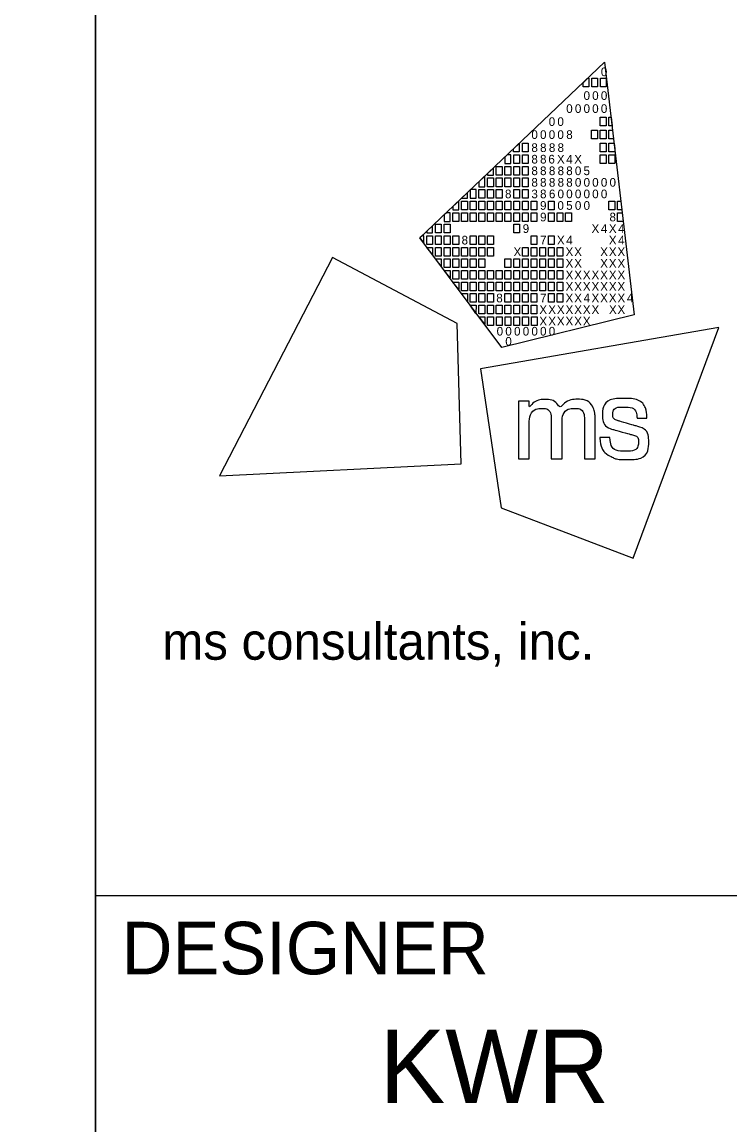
# Model space of a CAD drawing. Extents: x -0.2 to 34, y 6.6 to 28.6.
# Drawn here: x 31.86 to 33.207, y 8.674 to 10.773 of the extents above; entities that cross this region are included whole.
import ezdxf

# ---------------------------------------------------------------- set-up
doc = ezdxf.new("R2010")
doc.units = 0
for name, color, linetype in [('GE_X_Alignment', 7, 'Continuous'), ('SH_Border', 7, 'Continuous'), ('SH_Data', 7, 'Continuous')]:
    doc.layers.add(name, color=color, linetype=linetype)

msp = doc.modelspace()

# ---------------------------------------------------------------- linework, layer by layer
at = {"layer": 'GE_X_Alignment'}
msp.add_lwpolyline([(1.5, 28.1108), (32, 28.1108), (32, 7.1108), (1.5, 7.1108)], close=True, dxfattribs=at)
at = {"layer": 'SH_Border'}
for p, q in [((32, 7.1108), (32, 28.1108)), ((32, 9.1108), (33.5, 9.1108))]:
    msp.add_line(p, q, dxfattribs=at)
at = {"layer": 'SH_Data'}
for p, q in [((32.6175, 10.3627), (32.9688, 10.6969)), ((32.9688, 10.6969), (32.9688, 10.6969)), ((32.9688, 10.6969), (33.0253, 10.2159)), ((32.773, 10.1538), (32.6175, 10.3627)), ((33.0253, 10.2159), (32.773, 10.1538)), ((32.75, 10.1108), (32.75, 10.1108))]:
    msp.add_line(p, q, dxfattribs=at)
for points in [[(32.9279, 10.658), (32.9369, 10.6666), (32.9389, 10.6666), (32.9389, 10.6501), (32.9279, 10.6501)], [(32.9444, 10.6666), (32.9554, 10.6666), (32.9554, 10.6501), (32.9444, 10.6501)], [(32.9609, 10.6666), (32.9719, 10.6666), (32.9719, 10.6501), (32.9609, 10.6501)], [(32.9606, 10.5923), (32.9716, 10.5923), (32.9716, 10.5757), (32.9606, 10.5757)], [(32.9771, 10.5923), (32.9811, 10.5923), (32.983, 10.5757), (32.9771, 10.5757)], [(32.9441, 10.5675), (32.9551, 10.5675), (32.9551, 10.551), (32.9441, 10.551)], [(32.9606, 10.5675), (32.9716, 10.5675), (32.9716, 10.551), (32.9606, 10.551)], [(32.9771, 10.5675), (32.984, 10.5675), (32.9859, 10.551), (32.9771, 10.551)], [(32.7953, 10.5319), (32.8064, 10.5424), (32.8064, 10.5262), (32.7953, 10.5262)], [(32.8123, 10.5427), (32.8233, 10.5427), (32.8233, 10.5262), (32.8123, 10.5262)], [(32.9606, 10.5427), (32.9716, 10.5427), (32.9716, 10.5262), (32.9606, 10.5262)], [(32.9771, 10.5427), (32.9869, 10.5427), (32.9881, 10.5326), (32.9881, 10.5262), (32.9771, 10.5262)], [(32.7958, 10.5207), (32.8068, 10.5207), (32.8068, 10.5042), (32.7958, 10.5042)], [(32.8123, 10.5207), (32.8233, 10.5207), (32.8233, 10.5042), (32.8123, 10.5042)], [(32.9606, 10.5207), (32.9716, 10.5207), (32.9716, 10.5042), (32.9606, 10.5042)], [(32.9771, 10.5207), (32.9881, 10.5207), (32.9881, 10.5042), (32.9771, 10.5042)], [(32.7627, 10.4987), (32.7737, 10.4987), (32.7737, 10.4822), (32.7627, 10.4822)], [(32.7793, 10.4987), (32.7903, 10.4987), (32.7903, 10.4822), (32.7793, 10.4822)], [(32.7958, 10.4987), (32.8068, 10.4987), (32.8068, 10.4822), (32.7958, 10.4822)], [(32.8123, 10.4987), (32.8233, 10.4987), (32.8233, 10.4822), (32.8123, 10.4822)], [(32.7462, 10.4767), (32.7572, 10.4767), (32.7572, 10.4601), (32.7462, 10.4601)], [(32.7627, 10.4767), (32.7737, 10.4767), (32.7737, 10.4601), (32.7627, 10.4601)], [(32.7793, 10.4767), (32.7903, 10.4767), (32.7903, 10.4601), (32.7793, 10.4601)], [(32.7958, 10.4767), (32.8068, 10.4767), (32.8068, 10.4601), (32.7958, 10.4601)], [(32.8123, 10.4767), (32.8233, 10.4767), (32.8233, 10.4601), (32.8123, 10.4601)], [(32.7297, 10.4546), (32.7407, 10.4546), (32.7407, 10.4381), (32.7297, 10.4381)], [(32.7462, 10.4546), (32.7572, 10.4546), (32.7572, 10.4381), (32.7462, 10.4381)], [(32.7627, 10.4546), (32.7737, 10.4546), (32.7737, 10.4381), (32.7627, 10.4381)], [(32.7958, 10.4546), (32.8068, 10.4546), (32.8068, 10.4381), (32.7958, 10.4381)], [(32.8123, 10.4546), (32.8233, 10.4546), (32.8233, 10.4381), (32.8123, 10.4381)], [(32.6967, 10.4326), (32.7077, 10.4326), (32.7077, 10.4161), (32.6967, 10.4161)], [(32.7132, 10.4326), (32.7242, 10.4326), (32.7242, 10.4161), (32.7132, 10.4161)], [(32.7297, 10.4326), (32.7407, 10.4326), (32.7407, 10.4161), (32.7297, 10.4161)], [(32.7462, 10.4326), (32.7572, 10.4326), (32.7572, 10.4161), (32.7462, 10.4161)], [(32.7627, 10.4326), (32.7737, 10.4326), (32.7737, 10.4161), (32.7627, 10.4161)], [(32.7793, 10.4326), (32.7903, 10.4326), (32.7903, 10.4161), (32.7793, 10.4161)], [(32.7958, 10.4326), (32.8068, 10.4326), (32.8068, 10.4161), (32.7958, 10.4161)], [(32.8123, 10.4326), (32.8233, 10.4326), (32.8233, 10.4161), (32.8123, 10.4161)], [(32.8288, 10.4326), (32.8398, 10.4326), (32.8398, 10.4161), (32.8288, 10.4161)], [(32.8618, 10.4326), (32.8728, 10.4326), (32.8728, 10.4161), (32.8618, 10.4161)], [(32.9771, 10.4326), (32.9881, 10.4326), (32.9881, 10.4161), (32.9771, 10.4161)], [(32.9935, 10.4326), (32.9998, 10.4326), (33.0018, 10.4161), (32.9935, 10.4161)], [(32.6802, 10.4106), (32.6912, 10.4106), (32.6912, 10.3941), (32.6802, 10.3941)], [(32.6967, 10.4106), (32.7077, 10.4106), (32.7077, 10.3941), (32.6967, 10.3941)], [(32.7132, 10.4106), (32.7242, 10.4106), (32.7242, 10.3941), (32.7132, 10.3941)], [(32.7297, 10.4106), (32.7407, 10.4106), (32.7407, 10.3941), (32.7297, 10.3941)], [(32.7462, 10.4106), (32.7572, 10.4106), (32.7572, 10.3941), (32.7462, 10.3941)], [(32.7627, 10.4106), (32.7737, 10.4106), (32.7737, 10.3941), (32.7627, 10.3941)], [(32.7793, 10.4106), (32.7903, 10.4106), (32.7903, 10.3941), (32.7793, 10.3941)], [(32.7958, 10.4106), (32.8068, 10.4106), (32.8068, 10.3941), (32.7958, 10.3941)], [(32.8123, 10.4106), (32.8233, 10.4106), (32.8233, 10.3941), (32.8123, 10.3941)], [(32.8288, 10.4106), (32.8398, 10.4106), (32.8398, 10.3941), (32.8288, 10.3941)], [(32.8618, 10.4106), (32.8728, 10.4106), (32.8728, 10.3941), (32.8618, 10.3941)], [(32.8783, 10.4106), (32.8893, 10.4106), (32.8893, 10.3941), (32.8783, 10.3941)], [(32.8947, 10.4106), (32.9057, 10.4106), (32.9057, 10.3941), (32.8947, 10.3941)], [(32.9935, 10.4106), (33.0024, 10.4106), (33.0044, 10.3941), (32.9935, 10.3941)], [(32.6471, 10.3886), (32.6581, 10.3886), (32.6581, 10.3721), (32.6471, 10.3721)], [(32.6637, 10.3886), (32.6747, 10.3886), (32.6747, 10.3721), (32.6637, 10.3721)], [(32.7958, 10.3886), (32.8068, 10.3886), (32.8068, 10.3721), (32.7958, 10.3721)], [(32.6306, 10.3666), (32.6416, 10.3666), (32.6416, 10.3501), (32.6306, 10.3501)], [(32.6471, 10.3666), (32.6581, 10.3666), (32.6581, 10.3501), (32.6471, 10.3501)], [(32.6637, 10.3666), (32.6747, 10.3666), (32.6747, 10.3501), (32.6637, 10.3501)], [(32.6802, 10.3666), (32.6912, 10.3666), (32.6912, 10.3501), (32.6802, 10.3501)], [(32.7132, 10.3666), (32.7242, 10.3666), (32.7242, 10.3501), (32.7132, 10.3501)], [(32.7297, 10.3666), (32.7407, 10.3666), (32.7407, 10.3501), (32.7297, 10.3501)], [(32.7462, 10.3666), (32.7572, 10.3666), (32.7572, 10.3501), (32.7462, 10.3501)], [(32.8288, 10.3666), (32.8398, 10.3666), (32.8398, 10.3501), (32.8288, 10.3501)], [(32.8618, 10.3666), (32.8728, 10.3666), (32.8728, 10.3501), (32.8618, 10.3501)], [(32.6306, 10.3445), (32.6416, 10.3445), (32.6416, 10.3308)], [(32.6471, 10.3445), (32.6581, 10.3445), (32.6581, 10.328), (32.6471, 10.328)], [(32.6637, 10.3445), (32.6747, 10.3445), (32.6747, 10.328), (32.6637, 10.328)], [(32.6802, 10.3445), (32.6912, 10.3445), (32.6912, 10.328), (32.6802, 10.328)], [(32.6967, 10.3445), (32.7077, 10.3445), (32.7077, 10.328), (32.6967, 10.328)], [(32.7132, 10.3445), (32.7242, 10.3445), (32.7242, 10.328), (32.7132, 10.328)], [(32.7297, 10.3445), (32.7407, 10.3445), (32.7407, 10.328), (32.7297, 10.328)], [(32.7462, 10.3445), (32.7572, 10.3445), (32.7572, 10.328), (32.7462, 10.328)], [(32.8123, 10.3445), (32.8233, 10.3445), (32.8233, 10.328), (32.8123, 10.328)], [(32.8288, 10.3445), (32.8398, 10.3445), (32.8398, 10.328), (32.8288, 10.328)], [(32.8453, 10.3445), (32.8563, 10.3445), (32.8563, 10.328), (32.8453, 10.328)], [(32.8618, 10.3445), (32.8728, 10.3445), (32.8728, 10.328), (32.8618, 10.328)], [(32.8783, 10.3445), (32.8893, 10.3445), (32.8893, 10.328), (32.8783, 10.328)], [(32.6471, 10.3225), (32.6581, 10.3225), (32.6581, 10.3088)], [(32.6637, 10.3225), (32.6747, 10.3225), (32.6747, 10.306), (32.6637, 10.306)], [(32.6802, 10.3225), (32.6912, 10.3225), (32.6912, 10.306), (32.6802, 10.306)], [(32.6967, 10.3225), (32.7077, 10.3225), (32.7077, 10.306), (32.6967, 10.306)], [(32.7132, 10.3225), (32.7242, 10.3225), (32.7242, 10.306), (32.7132, 10.306)], [(32.7297, 10.3225), (32.7407, 10.3225), (32.7407, 10.306), (32.7297, 10.306)], [(32.7793, 10.3225), (32.7903, 10.3225), (32.7903, 10.306), (32.7793, 10.306)], [(32.7958, 10.3225), (32.8068, 10.3225), (32.8068, 10.306), (32.7958, 10.306)], [(32.8123, 10.3225), (32.8233, 10.3225), (32.8233, 10.306), (32.8123, 10.306)], [(32.8288, 10.3225), (32.8398, 10.3225), (32.8398, 10.306), (32.8288, 10.306)], [(32.8453, 10.3225), (32.8563, 10.3225), (32.8563, 10.306), (32.8453, 10.306)], [(32.8618, 10.3225), (32.8728, 10.3225), (32.8728, 10.306), (32.8618, 10.306)], [(32.8783, 10.3225), (32.8893, 10.3225), (32.8893, 10.306), (32.8783, 10.306)], [(32.6637, 10.3005), (32.6747, 10.3005), (32.6747, 10.2868)], [(32.6747, 10.3005), (32.6747, 10.3005), (32.6747, 10.3005)], [(32.6802, 10.3005), (32.6912, 10.3005), (32.6912, 10.284), (32.6802, 10.284)], [(32.6967, 10.3005), (32.7077, 10.3005), (32.7077, 10.284), (32.6967, 10.284)], [(32.7132, 10.3005), (32.7242, 10.3005), (32.7242, 10.284), (32.7132, 10.284)], [(32.7297, 10.3005), (32.7407, 10.3005), (32.7407, 10.284), (32.7297, 10.284)], [(32.7462, 10.3005), (32.7572, 10.3005), (32.7572, 10.284), (32.7462, 10.284)], [(32.7627, 10.3005), (32.7737, 10.3005), (32.7737, 10.284), (32.7627, 10.284)], [(32.7793, 10.3005), (32.7903, 10.3005), (32.7903, 10.284), (32.7793, 10.284)], [(32.7958, 10.3005), (32.8068, 10.3005), (32.8068, 10.284), (32.7958, 10.284)], [(32.8123, 10.3005), (32.8233, 10.3005), (32.8233, 10.284), (32.8123, 10.284)], [(32.8288, 10.3005), (32.8398, 10.3005), (32.8398, 10.284), (32.8288, 10.284)], [(32.8453, 10.3005), (32.8563, 10.3005), (32.8563, 10.284), (32.8453, 10.284)], [(32.8618, 10.3005), (32.8728, 10.3005), (32.8728, 10.284), (32.8618, 10.284)], [(32.8783, 10.3005), (32.8893, 10.3005), (32.8893, 10.284), (32.8783, 10.284)], [(32.6802, 10.2785), (32.6912, 10.2785), (32.6912, 10.2647)], [(32.6967, 10.2785), (32.7077, 10.2785), (32.7077, 10.262), (32.6967, 10.262)], [(32.7132, 10.2785), (32.7242, 10.2785), (32.7242, 10.262), (32.7132, 10.262)], [(32.7297, 10.2785), (32.7407, 10.2785), (32.7407, 10.262), (32.7297, 10.262)], [(32.7462, 10.2785), (32.7572, 10.2785), (32.7572, 10.262), (32.7462, 10.262)], [(32.7627, 10.2785), (32.7737, 10.2785), (32.7737, 10.262), (32.7627, 10.262)], [(32.7793, 10.2785), (32.7903, 10.2785), (32.7903, 10.262), (32.7793, 10.262)], [(32.7958, 10.2785), (32.8068, 10.2785), (32.8068, 10.262), (32.7958, 10.262)], [(32.8123, 10.2785), (32.8233, 10.2785), (32.8233, 10.262), (32.8123, 10.262)], [(32.8288, 10.2785), (32.8398, 10.2785), (32.8398, 10.262), (32.8288, 10.262)], [(32.8453, 10.2785), (32.8563, 10.2785), (32.8563, 10.262), (32.8453, 10.262)], [(32.8618, 10.2785), (32.8728, 10.2785), (32.8728, 10.262), (32.8618, 10.262)], [(32.8783, 10.2785), (32.8893, 10.2785), (32.8893, 10.262), (32.8783, 10.262)], [(32.7077, 10.2413), (32.6965, 10.2565), (32.7077, 10.2565)], [(32.7132, 10.2565), (32.7242, 10.2565), (32.7242, 10.24), (32.7132, 10.24)], [(32.7297, 10.2565), (32.7407, 10.2565), (32.7407, 10.24), (32.7297, 10.24)], [(32.7462, 10.2565), (32.7572, 10.2565), (32.7572, 10.24), (32.7462, 10.24)], [(32.7793, 10.2565), (32.7903, 10.2565), (32.7903, 10.24), (32.7793, 10.24)], [(32.7958, 10.2565), (32.8068, 10.2565), (32.8068, 10.24), (32.7958, 10.24)], [(32.8123, 10.2565), (32.8233, 10.2565), (32.8233, 10.24), (32.8123, 10.24)], [(32.8288, 10.2565), (32.8398, 10.2565), (32.8398, 10.24), (32.8288, 10.24)], [(32.8618, 10.2565), (32.8728, 10.2565), (32.8728, 10.24), (32.8618, 10.24)], [(32.8783, 10.2565), (32.8893, 10.2565), (32.8893, 10.24), (32.8783, 10.24)], [(32.724, 10.219), (32.7132, 10.2345), (32.7242, 10.2345)], [(32.7297, 10.2345), (32.7407, 10.2345), (32.7407, 10.2179), (32.7297, 10.2179)], [(32.7462, 10.2345), (32.7572, 10.2345), (32.7572, 10.2179), (32.7462, 10.2179)], [(32.7627, 10.2345), (32.7737, 10.2345), (32.7737, 10.2179), (32.7627, 10.2179)], [(32.7793, 10.2345), (32.7903, 10.2345), (32.7903, 10.2179), (32.7793, 10.2179)], [(32.7958, 10.2345), (32.8068, 10.2345), (32.8068, 10.2179), (32.7958, 10.2179)], [(32.8123, 10.2345), (32.8233, 10.2345), (32.8233, 10.2179), (32.8123, 10.2179)], [(32.8288, 10.2345), (32.8398, 10.2345), (32.8398, 10.2179), (32.8288, 10.2179)], [(32.7302, 10.2125), (32.7407, 10.2125), (32.7408, 10.1983)], [(32.7463, 10.2125), (32.7573, 10.2125), (32.7573, 10.196), (32.7463, 10.196)], [(32.763, 10.2125), (32.774, 10.2125), (32.774, 10.196), (32.763, 10.196)], [(32.7794, 10.2125), (32.7904, 10.2125), (32.7904, 10.196), (32.7794, 10.196)], [(32.796, 10.2125), (32.807, 10.2125), (32.807, 10.196), (32.796, 10.196)], [(32.8129, 10.2124), (32.8239, 10.2124), (32.8239, 10.1959), (32.8129, 10.1959)], [(32.8296, 10.2124), (32.8406, 10.2124), (32.8406, 10.1959), (32.8296, 10.1959)]]:
    msp.add_lwpolyline(points, close=True, dxfattribs=at)
for points in [[(32.7903, 10.5207), (32.7836, 10.5207), (32.7793, 10.5166), (32.7793, 10.5042), (32.7903, 10.5042), (32.7903, 10.5207)], [(32.7407, 10.4799), (32.7297, 10.4694), (32.7297, 10.4601), (32.7407, 10.4601), (32.7407, 10.4799)], [(32.7572, 10.4956), (32.7462, 10.4852), (32.7462, 10.4822), (32.7572, 10.4822), (32.7572, 10.4956)], [(32.7077, 10.4485), (32.6968, 10.4381), (32.7077, 10.4381), (32.7077, 10.4485)], [(32.7242, 10.4546), (32.7141, 10.4546), (32.7132, 10.4537), (32.7132, 10.4381), (32.7242, 10.4381), (32.7242, 10.4546)], [(32.6912, 10.4328), (32.6802, 10.4223), (32.6802, 10.4161), (32.6912, 10.4161), (32.6912, 10.4328)], [(32.6747, 10.4106), (32.6679, 10.4106), (32.6637, 10.4066), (32.6637, 10.3941), (32.6747, 10.3941), (32.6747, 10.4106)], [(32.6416, 10.3857), (32.6306, 10.3752), (32.6306, 10.3721), (32.6416, 10.3721), (32.6416, 10.3857)], [(32.6251, 10.3666), (32.6216, 10.3666), (32.6175, 10.3627), (32.6251, 10.3525), (32.6251, 10.3666)], [(32.4512, 10.3256), (32.2359, 9.9096), (32.6956, 9.9323), (32.6884, 10.1999), (32.4512, 10.3256)], [(33.0229, 9.753), (33.1859, 10.1922), (32.7324, 10.1137), (32.7722, 9.8489), (33.0229, 9.753)]]:
    msp.add_lwpolyline(points, dxfattribs=at)
for points in [[(32.9595, 9.9816), (32.9595, 9.9816), (32.9595, 9.9825), (32.9595, 9.9825), (32.9595, 9.9825), (32.9603, 9.9825), (32.9603, 9.9825), (32.9603, 9.9825), (32.9783, 9.9825), (32.9783, 9.9825), (32.9783, 9.9825), (32.9789, 9.9825), (32.9789, 9.9825), (32.9789, 9.9825), (32.979, 9.9818), (32.979, 9.9818), (32.9803, 9.9662), (32.9887, 9.9568), (33.009, 9.9568), (33.0273, 9.9568), (33.0333, 9.9662), (33.0333, 9.9739), (33.0333, 9.984), (33.0256, 9.9866), (33.0175, 9.9888), (33.0175, 9.9888), (32.987, 9.9975), (32.987, 9.9975), (32.972, 10.0017), (32.9648, 10.0127), (32.9648, 10.025), (32.9648, 10.0411), (32.9768, 10.057), (33.0052, 10.057), (33.0348, 10.057), (33.0489, 10.0393), (33.0489, 10.0202), (33.0489, 10.0202), (33.0489, 10.0195), (33.0489, 10.0195), (33.0489, 10.0195), (33.0482, 10.0195), (33.0482, 10.0195), (33.0482, 10.0195), (33.0312, 10.0195), (33.0312, 10.0195), (33.0312, 10.0195), (33.0305, 10.0195), (33.0305, 10.0195), (33.0305, 10.0195), (33.0305, 10.0202), (33.0305, 10.0202), (33.0301, 10.0316), (33.0226, 10.0407), (33.0056, 10.0407), (32.9891, 10.0407), (32.9843, 10.0326), (32.9843, 10.0265), (32.9843, 10.0216), (32.9869, 10.0167), (32.9959, 10.0141), (32.9959, 10.0141), (33.0255, 10.0056), (33.0255, 10.0056), (33.0462, 9.9997), (33.0527, 9.9885), (33.0527, 9.9747), (33.0527, 9.957), (33.041, 9.9406), (33.0087, 9.9406), (32.9952, 9.9406), (32.9877, 9.9429), (32.9823, 9.9456), (32.969, 9.9522), (32.9609, 9.9644), (32.9595, 9.9816)], [(32.8048, 9.9423), (32.8048, 9.9423), (32.8048, 10.0517), (32.8048, 10.0517), (32.8048, 10.0517), (32.8255, 10.0517), (32.8255, 10.0517), (32.8255, 10.0517), (32.8255, 10.0405), (32.8255, 10.0405), (32.8346, 10.0507), (32.8457, 10.0552), (32.8555, 10.0552), (32.8688, 10.0552), (32.8791, 10.048), (32.8837, 10.0374), (32.8915, 10.0488), (32.905, 10.0554), (32.9166, 10.0554), (32.9325, 10.0554), (32.9451, 10.0458), (32.9494, 10.032), (32.9494, 10.032), (32.9494, 10.032), (32.9494, 10.0319), (32.9501, 10.0297), (32.9506, 10.028), (32.9506, 10.0178), (32.9506, 10.0178), (32.9506, 9.9422), (32.9506, 9.9422), (32.9506, 9.9422), (32.9303, 9.9422), (32.9303, 9.9422), (32.9303, 9.9422), (32.9303, 10.0156), (32.9303, 10.0156), (32.9303, 10.0309), (32.9219, 10.0382), (32.911, 10.0382), (32.8995, 10.0382), (32.8879, 10.0278), (32.8879, 10.0109), (32.8879, 10.0109), (32.8879, 9.9423), (32.8879, 9.9423), (32.8879, 9.9423), (32.8674, 9.9423), (32.8674, 9.9423), (32.8674, 9.9423), (32.8674, 10.0167), (32.8674, 10.0167), (32.8674, 10.0311), (32.8588, 10.0382), (32.8496, 10.0382), (32.8384, 10.0382), (32.8254, 10.0278), (32.8254, 10.007), (32.8254, 10.007), (32.8254, 9.9423), (32.8254, 9.9423), (32.8254, 9.9423), (32.8048, 9.9423), (32.8048, 9.9423)]]:
    msp.add_open_spline(points, degree=3, dxfattribs=at)

# ---------------------------------------------------------------- texts
for s, height, p in [('0', 0.0165, (32.9617, 10.6705)), ('0', 0.0165, (32.9288, 10.6253)), ('0', 0.0165, (32.9452, 10.6253)), ('0', 0.0165, (32.9617, 10.6253)), ('0', 0.0165, (32.8958, 10.6005)), ('0', 0.0165, (32.9123, 10.6005)), ('0', 0.0165, (32.9288, 10.6005)), ('0', 0.0165, (32.9452, 10.6005)), ('0', 0.0165, (32.9617, 10.6005)), ('0', 0.0165, (32.8625, 10.5757)), ('0', 0.0165, (32.879, 10.5757)), ('0', 0.0165, (32.8295, 10.551)), ('0', 0.0165, (32.846, 10.551)), ('0', 0.0165, (32.8625, 10.551)), ('0', 0.0165, (32.879, 10.551)), ('8', 0.0165, (32.8958, 10.551)), ('8', 0.0165, (32.8295, 10.5262)), ('8', 0.0165, (32.846, 10.5262)), ('8', 0.0165, (32.8628, 10.5262)), ('8', 0.0165, (32.8793, 10.5262)), ('8', 0.0165, (32.8295, 10.5042)), ('8', 0.0165, (32.846, 10.5042)), ('6', 0.0165, (32.8618, 10.5042)), ('X', 0.0165, (32.8781, 10.5042)), ('4', 0.0165, (32.8958, 10.5042)), ('X', 0.0165, (32.911, 10.5042)), ('8', 0.0165, (32.8295, 10.4821)), ('8', 0.0165, (32.846, 10.4821)), ('8', 0.0165, (32.8628, 10.4821)), ('8', 0.0165, (32.8794, 10.4821)), ('8', 0.0165, (32.8958, 10.4821)), ('0', 0.0165, (32.9123, 10.4821)), ('5', 0.0165, (32.9287, 10.4821)), ('8', 0.0165, (32.8295, 10.4601)), ('8', 0.0165, (32.846, 10.4601)), ('8', 0.0165, (32.8628, 10.4601)), ('8', 0.0165, (32.8794, 10.4601)), ('8', 0.0165, (32.8958, 10.4601)), ('0', 0.0165, (32.9123, 10.4601)), ('0', 0.0165, (32.9288, 10.4601)), ('0', 0.0165, (32.9452, 10.4601)), ('0', 0.0165, (32.9617, 10.4601)), ('0', 0.0165, (32.9782, 10.4601)), ('8', 0.0165, (32.7793, 10.4381)), ('3', 0.0165, (32.8295, 10.4381)), ('8', 0.0165, (32.846, 10.4381)), ('6', 0.0165, (32.8629, 10.4381)), ('0', 0.0165, (32.8793, 10.4381)), ('0', 0.0165, (32.8958, 10.4381)), ('0', 0.0165, (32.9123, 10.4381)), ('0', 0.0165, (32.9288, 10.4381)), ('0', 0.0165, (32.9452, 10.4381)), ('0', 0.0165, (32.9617, 10.4381)), ('9', 0.0165, (32.846, 10.4161)), ('0', 0.0165, (32.879, 10.4161)), ('5', 0.0165, (32.8957, 10.4161)), ('0', 0.0165, (32.9123, 10.4161)), ('0', 0.0165, (32.9288, 10.4161)), ('9', 0.0165, (32.846, 10.3941)), ('8', 0.0165, (32.9781, 10.3941)), ('9', 0.0165, (32.813, 10.3721)), ('X', 0.0165, (32.9439, 10.3721)), ('4', 0.0165, (32.9617, 10.3721)), ('X', 0.0165, (32.9769, 10.3721)), ('4', 0.0165, (32.9946, 10.3721)), ('8', 0.0165, (32.6967, 10.3501)), ('7', 0.0165, (32.846, 10.3501)), ('X', 0.0165, (32.8781, 10.3501)), ('4', 0.0165, (32.8958, 10.3501)), ('X', 0.0165, (32.9769, 10.3501)), ('4', 0.0165, (32.9946, 10.3501)), ('X', 0.0165, (32.7955, 10.328)), ('X', 0.0165, (32.8945, 10.328)), ('X', 0.0165, (32.911, 10.328)), ('X', 0.0165, (32.9604, 10.328)), ('X', 0.0165, (32.9769, 10.328)), ('X', 0.0165, (32.9933, 10.328)), ('X', 0.0165, (32.8945, 10.306)), ('X', 0.0165, (32.911, 10.306)), ('X', 0.0165, (32.9604, 10.306)), ('X', 0.0165, (32.9769, 10.306)), ('X', 0.0165, (32.9933, 10.306)), ('X', 0.0165, (32.8945, 10.284)), ('X', 0.0165, (32.911, 10.284)), ('X', 0.0165, (32.9274, 10.284)), ('X', 0.0165, (32.9439, 10.284)), ('X', 0.0165, (32.9604, 10.284)), ('X', 0.0165, (32.9769, 10.284)), ('X', 0.0165, (32.9933, 10.284)), ('X', 0.0165, (32.8945, 10.262)), ('X', 0.0165, (32.911, 10.262)), ('X', 0.0165, (32.9274, 10.262)), ('X', 0.0165, (32.9439, 10.262)), ('X', 0.0165, (32.9604, 10.262)), ('X', 0.0165, (32.9769, 10.262)), ('X', 0.0165, (32.9933, 10.262)), ('8', 0.0165, (32.7627, 10.24)), ('7', 0.0165, (32.846, 10.24)), ('X', 0.0165, (32.8945, 10.24)), ('X', 0.0165, (32.911, 10.24)), ('4', 0.0165, (32.9288, 10.24)), ('X', 0.0165, (32.9439, 10.24)), ('X', 0.0165, (32.9604, 10.24)), ('X', 0.0165, (32.9769, 10.24)), ('X', 0.0165, (32.9933, 10.24)), ('4', 0.0165, (33.0111, 10.24)), ('X', 0.0165, (32.8447, 10.2179)), ('X', 0.0165, (32.8616, 10.2179)), ('X', 0.0165, (32.878, 10.2179)), ('X', 0.0165, (32.8945, 10.2179)), ('X', 0.0165, (32.911, 10.2179)), ('X', 0.0165, (32.9274, 10.2179)), ('X', 0.0165, (32.9439, 10.2179)), ('X', 0.0165, (32.9771, 10.2179)), ('X', 0.0165, (32.9933, 10.2179)), ('X', 0.0165, (32.8447, 10.1959)), ('X', 0.0165, (32.8616, 10.1959)), ('X', 0.0165, (32.878, 10.1959)), ('X', 0.0165, (32.8945, 10.1959)), ('X', 0.0165, (32.911, 10.1959)), ('X', 0.0165, (32.9274, 10.1959)), ('0', 0.0165, (32.7634, 10.1767)), ('0', 0.0165, (32.7799, 10.1767)), ('0', 0.0165, (32.7965, 10.1767)), ('0', 0.0165, (32.813, 10.1767)), ('0', 0.0165, (32.8295, 10.1767)), ('0', 0.0165, (32.846, 10.1767)), ('0', 0.0165, (32.8625, 10.1767)), ('0', 0.0165, (32.7799, 10.1575)), ('ms consultants, inc.', 0.07, (32.1273, 9.5597))]:
    msp.add_text(s, height=height, rotation=360, dxfattribs=at).set_placement(p)
for s, height, p in [('DESIGNER', 0.1, (32.05, 8.9608)), ('KWR', 0.14, (32.5407, 8.7158))]:
    msp.add_text(s, height=height, dxfattribs=at).set_placement(p)

doc.saveas('drawing.dxf')
